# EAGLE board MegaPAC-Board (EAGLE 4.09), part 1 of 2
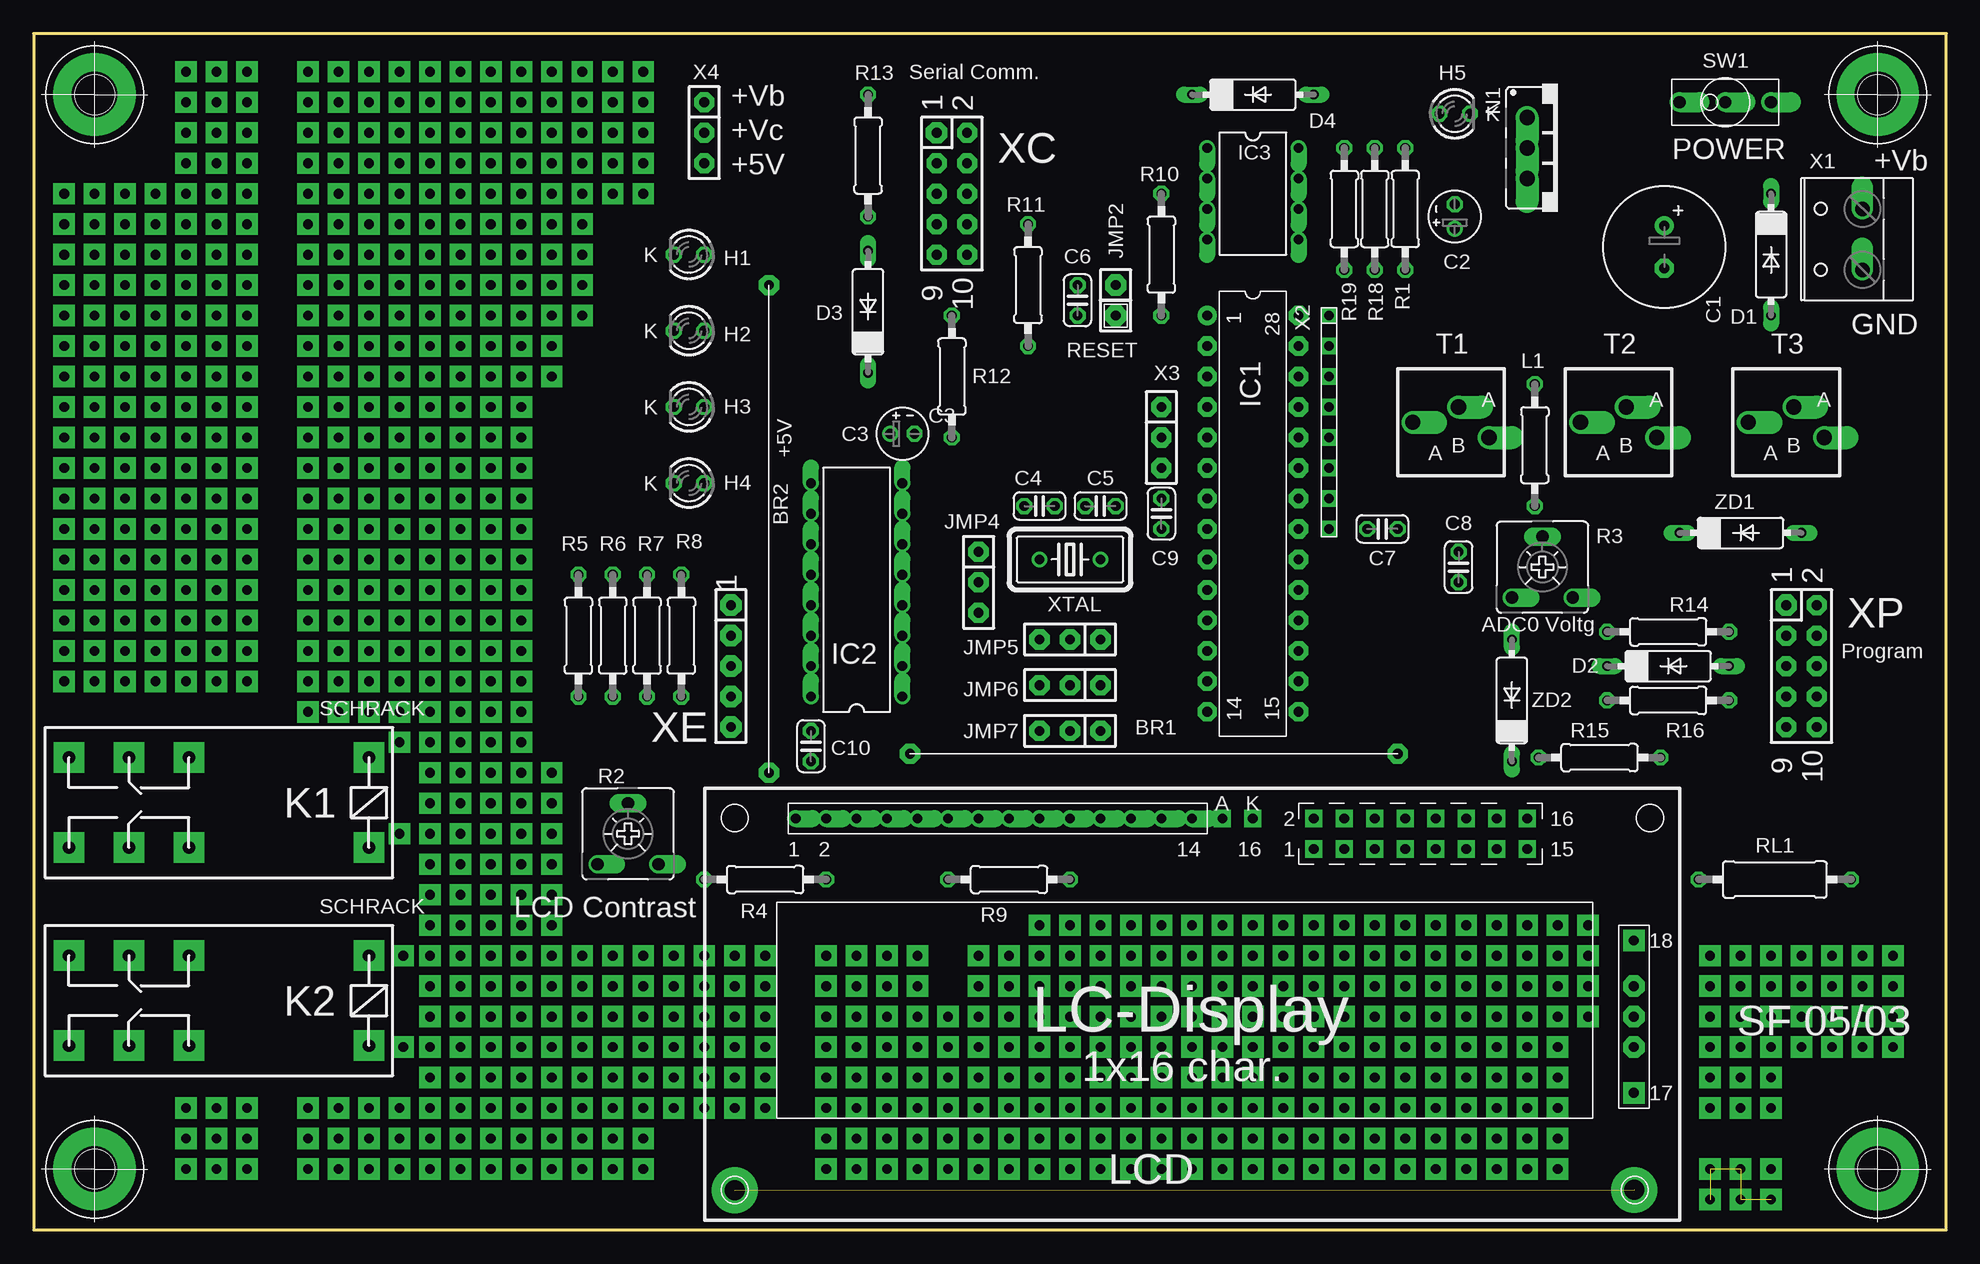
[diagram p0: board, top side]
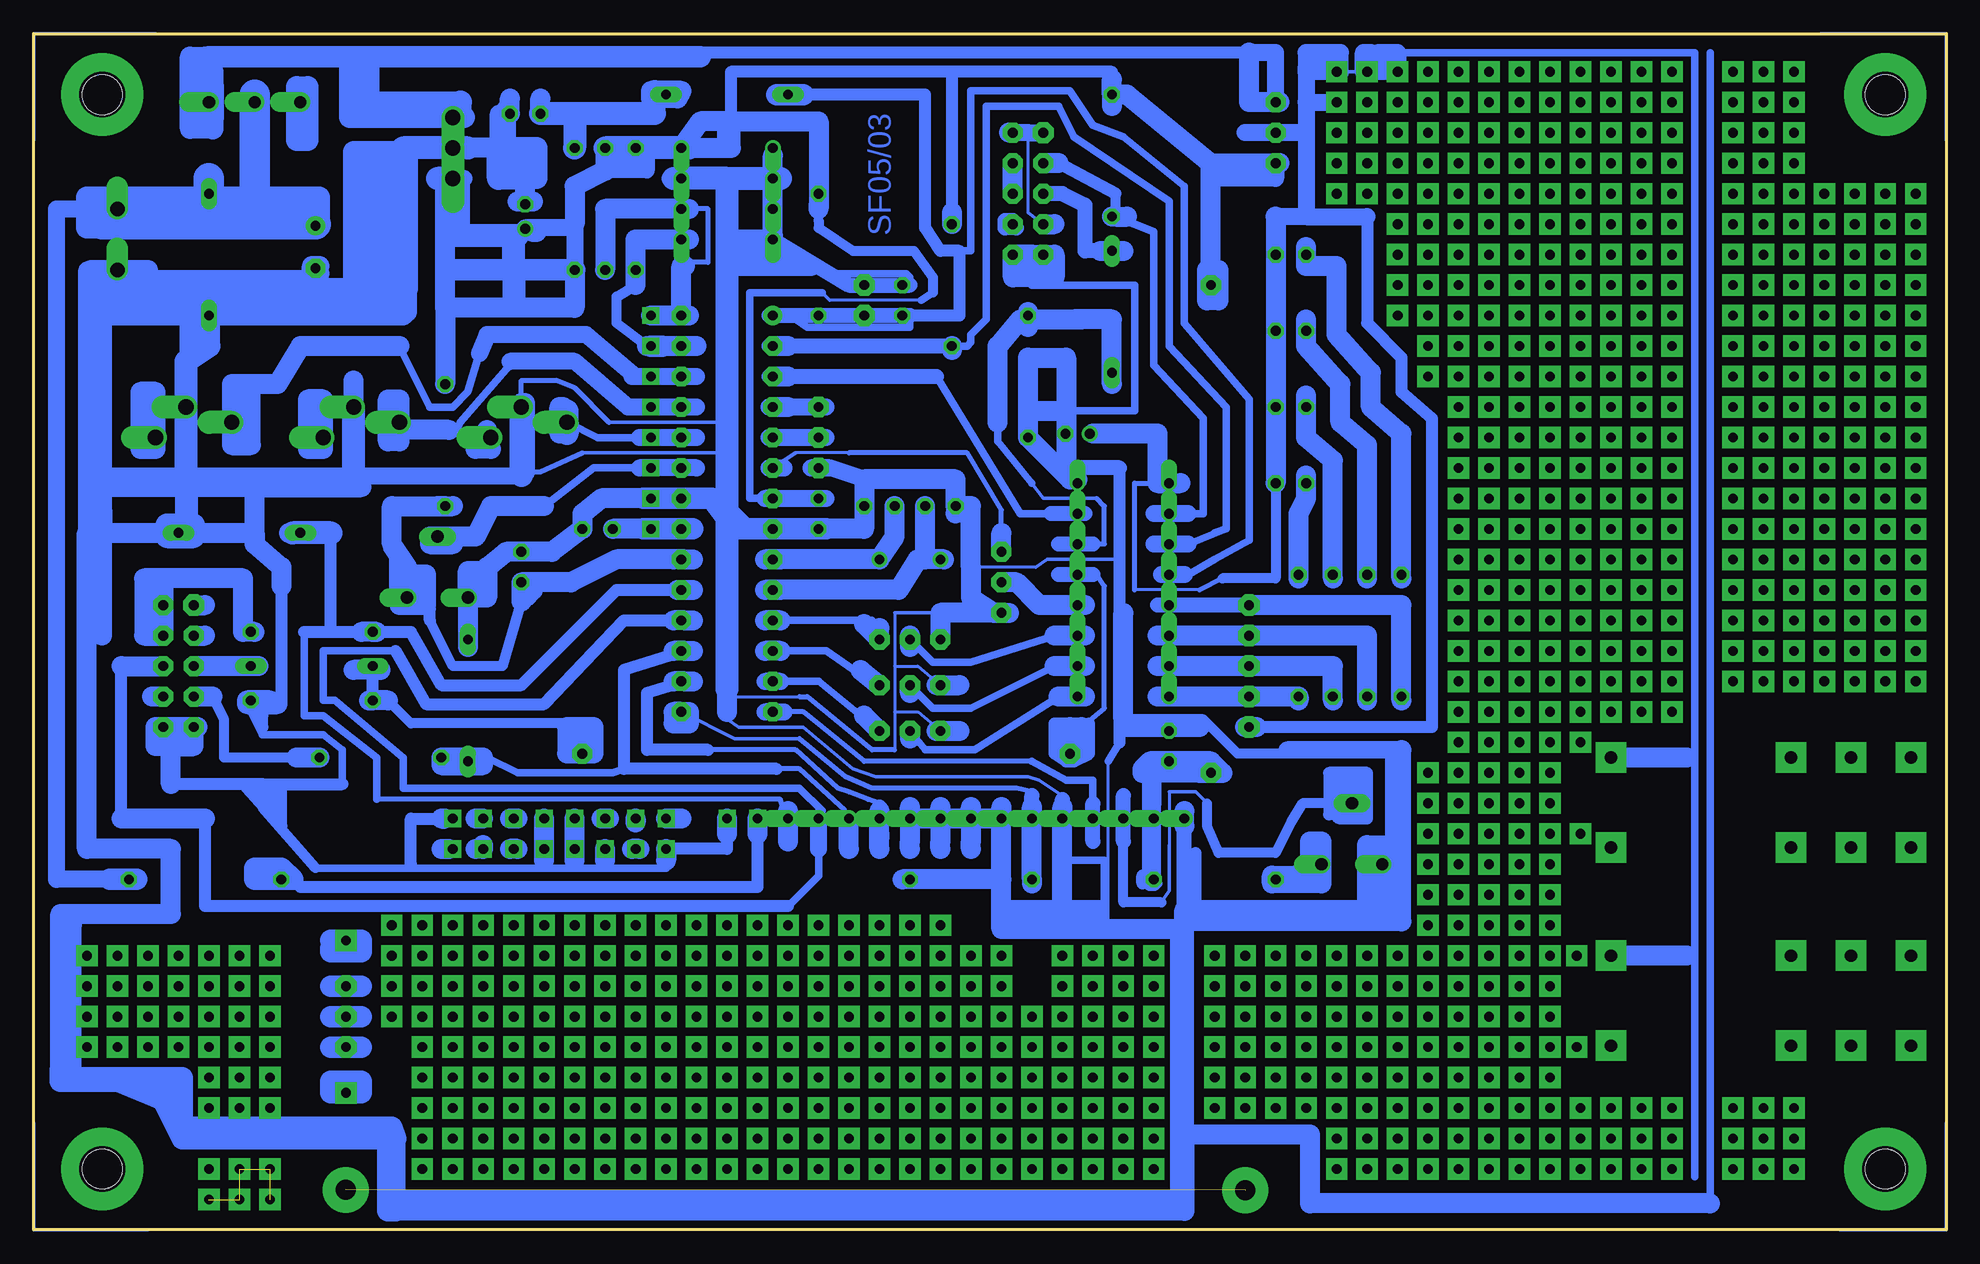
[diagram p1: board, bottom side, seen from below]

Size 159.38 x 99.69 mm. Coordinates in mm from the lower left corner, seen from the top.
Outline: 0,0 159.38,0 159.38,99.69 0,99.69 0,0
Copper layers used: Bottom

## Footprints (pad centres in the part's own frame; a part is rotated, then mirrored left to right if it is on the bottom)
40 = drill 0.813 pad 1.676 octagon: P$1 -20.32,0; P$2 20.32,0
E3,5-10 = drill 0.813 pad 1.6 round: + -1.778,0 | drill 0.813 pad 1.6 octagon: - 1.778,0
E2-4 = drill 0.813 pad 1.27 round: + -1.016,0 | drill 0.813 pad 1.27 octagon: - 1.016,0
C025-024X044 = drill 0.813 octagon: 1 -1.27,0; 2 1.27,0
DO07 = drill 0.813 long: A 5.08,0; C -5.08,0
B3,3 = drill 3.81 pad 6.858 round: P$1 0,0 | hole 3.302: 0,0
LED3MM = drill 0.813 octagon: A -1.27,0; K 1.27,0
DIL28-3 = drill 0.813 pad 1.6 round: 1 -16.51,-3.81 | drill 0.813 pad 1.6 octagon: 2 -13.97,-3.81; 3 -11.43,-3.81; 4 -8.89,-3.81; 5 -6.35,-3.81; 6 -3.81,-3.81; 7 -1.27,-3.81; 8 1.27,-3.81; 9 3.81,-3.81; 10 6.35,-3.81; 11 8.89,-3.81; 12 11.43,-3.81; 13 13.97,-3.81; 14 16.51,-3.81; 15 16.51,3.81; 16 13.97,3.81; 17 11.43,3.81; 18 8.89,3.81; 19 6.35,3.81; 20 3.81,3.81; 21 1.27,3.81; 22 -1.27,3.81; 23 -3.81,3.81; 24 -6.35,3.81; 25 -8.89,3.81; 26 -11.43,3.81; 27 -13.97,3.81; 28 -16.51,3.81
DIL16 = drill 0.813 offset: 1 -8.89,-3.81; 2 -6.35,-3.81; 3 -3.81,-3.81; 4 -1.27,-3.81; 5 1.27,-3.81; 6 3.81,-3.81; 7 6.35,-3.81; 8 8.89,-3.81; 9 8.89,3.81; 10 6.35,3.81; 11 3.81,3.81; 12 1.27,3.81; 13 -1.27,3.81; 14 -3.81,3.81; 15 -6.35,3.81; 16 -8.89,3.81
DIL08 = drill 0.813 offset: 1 -3.81,-3.81; 2 -1.27,-3.81; 3 1.27,-3.81; 4 3.81,-3.81; 5 3.81,3.81; 6 1.27,3.81; 7 -1.27,3.81; 8 -3.81,3.81
2X1X254 = drill 0.813 pad 1.778 octagon: P$1 0,0; P$2 2.54,0
3X1X254 = drill 0.813 pad 1.676 octagon: P$1 0,0; P$2 -2.54,0; P$3 2.54,0
RT-SCHRA = drill 1.016 pad 2.54 square: P$1 25,0; P$2 0,0; P$3 20,0; P$4 15,0; P$5 0,7.5; P$6 15,7.5; P$7 20,7.5; P$8 25,7.5
0207/10 = drill 0.813 octagon: 1 -5.08,0; 2 5.08,0
LCD1X16 = drill 0.813 pad 1.422 offset: P$1 5.08,-2.54; P$2 7.62,-2.54; P$3 10.16,-2.54; P$4 12.7,-2.54; P$5 15.24,-2.54; P$6 17.78,-2.54; P$7 20.32,-2.54; P$8 22.86,-2.54; P$9 25.4,-2.54; P$10 27.94,-2.54; P$11 30.48,-2.54; P$12 33.02,-2.54; P$13 35.56,-2.54; P$14 38.1,-2.54 | drill 0.813 pad 1.422 square: P$15 40.64,-2.54; P$16 43.18,-2.54; P$17 48.26,-2.54; P$18 50.8,-2.54; P$19 53.34,-2.54; P$20 55.88,-2.54; P$21 58.42,-2.54; P$22 60.96,-2.54; P$23 63.5,-2.54; P$24 66.04,-2.54; P$25 48.26,-5.08; P$26 50.8,-5.08; P$27 53.34,-5.08; P$28 55.88,-5.08; P$29 58.42,-5.08; P$30 60.96,-5.08; P$31 63.5,-5.08; P$32 66.04,-5.08 | drill 0.813 pad 1.778 octagon: P$33 74.93,-19.05; P$34 74.93,-16.51; P$35 74.93,-21.59 | drill 0.813 pad 1.778 square: P$36 74.93,-25.4; P$37 74.93,-12.7
78XXS_ = drill 1.27 pad 1.778 offset: GND 0,-2.54; IN -2.54,-2.54; OUT 2.54,-2.54
CA6V = drill 1.016 offset: A -2.54,-2.54; E 2.54,-2.54 | drill 1.016 long: S 0,2.54
0309/12 = drill 0.813 octagon: 1 -6.35,0; 2 6.35,0
MINISW = drill 1.016 pad 1.676 offset: P$1 0,0; P$2 3.81,0; P$3 -3.81,0
MPT-36 = drill 1.27 pad 1.905 offset: P$1 0.635,3.81; P$2 6.985,2.54; P$3 4.445,5.08
W237-132 = drill 1.194 offset: 1 -2.54,-0.635; 2 2.54,-0.635
8X1X254 = drill 0.813 pad 1.397 square: P$1 0,0; P$2 2.54,0; P$3 5.08,0; P$4 7.62,0; P$5 10.16,0; P$6 12.7,0; P$7 15.24,0; P$8 17.78,0
5X2X254 = drill 0.813 pad 1.676 octagon: P$1 2.54,0; P$3 5.08,0; P$4 7.62,0; P$5 10.16,0; P$6 0,0; P$7 2.54,2.54; P$8 0,2.54; P$9 5.08,2.54; P$10 7.62,2.54; P$11 10.16,2.54 | drill 0.813 pad 1.778 octagon: P$2 0,0
5X1X254 = drill 0.813 pad 1.778 octagon: P$1 2.54,0; P$2 0,0; P$3 5.08,0; P$4 7.62,0; P$5 10.16,0
HC18U-V = drill 0.813 round: 1 -2.54,0; 2 2.54,0

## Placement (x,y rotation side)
BR1  [40]  93.34,39.69 0 top
BR2  [40]  61.28,58.42 90 top
C1  [E3,5-10]  135.89,81.92 270 top
C2  [E2-4]  118.43,84.45 90 top
C3  [E2-4]  72.39,66.36 0 top
C4  [C025-024X044]  83.82,60.33 180 top
C5  [C025-024X044]  88.9,60.33 180 top
C6  [C025-024X044]  87,77.47 90 top
C7  [C025-024X044]  112.39,58.42 180 top
C8  [C025-024X044]  118.75,55.24 270 top
C9  [C025-024X044]  93.98,59.69 90 top
C10  [C025-024X044]  64.77,40.32 270 top
D1  [DO07]  144.78,81.28 270 top
D2  [DO07]  136.21,46.99 0 top
D3  [DO07]  69.53,76.52 90 top
D4  [DO07]  101.6,94.61 0 top
E$1  [B3,3]  5.08,94.61 0 top
E$2  [B3,3]  5.08,5.08 0 top
E$3  [B3,3]  153.67,5.08 0 top
E$4  [B3,3]  153.67,94.61 0 top
H1  [LED3MM]  54.61,81.28 180 top
H2  [LED3MM]  54.61,74.93 180 top
H3  [LED3MM]  54.61,68.58 180 top
H4  [LED3MM]  54.61,62.23 180 top
H5  [LED3MM]  118.43,93.03 0 top
IC1  ATmega8  [DIL28-3]  101.6,59.69 270 top
IC2  ULN2003  [DIL16]  68.58,53.34 90 top
IC3  X24C16  [DIL08]  101.6,86.36 270 top
JMP2  [2X1X254]  90.17,76.2 90 top
JMP4  [3X1X254]  78.74,53.98 270 top
JMP5  [3X1X254]  86.36,49.21 180 top
JMP6  [3X1X254]  86.36,45.4 180 top
JMP7  [3X1X254]  86.36,41.59 180 top
K1  [RT-SCHRA]  27.94,39.37 180 top
K2  [RT-SCHRA]  27.94,22.86 180 top
L1  [0207/10]  125.09,65.41 270 top
LCD  [LCD1X16]  58.42,36.83 0 top
N1  [78XXS_]  127,90.17 270 top
R1  [0207/10]  114.3,85.09 90 top
R2  [CA6V]  49.53,33.02 0 top
R3  [CA6V]  125.73,55.24 0 top
R4  [0207/10]  60.96,29.21 0 top
R5  [0207/10]  45.4,49.53 90 top
R6  [0207/10]  48.26,49.53 90 top
R7  [0207/10]  51.12,49.53 90 top
R8  [0207/10]  53.98,49.53 90 top
R9  [0207/10]  81.28,29.21 0 top
R10  [0207/10]  93.98,81.28 90 top
R11  [0207/10]  82.87,78.74 90 top
R12  [0207/10]  76.52,71.12 90 top
R13  [0207/10]  69.53,89.53 270 top
R14  [0207/10]  136.21,49.85 0 top
R15  [0207/10]  130.49,39.37 0 top
R16  [0207/10]  136.21,44.13 0 top
R18  [0207/10]  109.22,85.09 270 top
R19  [0207/10]  111.76,85.09 270 top
RL1  [0309/12]  145.1,29.21 0 top
SW1  [MINISW]  140.97,93.98 0 top
T1  [MPT-36]  114.3,63.5 0 top
T2  [MPT-36]  128.27,63.5 0 top
T3  [MPT-36]  142.24,63.5 0 top
X1  [W237-132]  151.76,82.55 90 top
X2  [8X1X254]  107.95,76.2 270 top
X3  [3X1X254]  93.98,66.04 270 top
X4  [3X1X254]  55.88,91.44 270 top
XC  [5X2X254]  75.25,91.44 270 top
XE  [5X1X254]  58.1,52.07 270 top
XP  [5X2X254]  146.05,52.07 270 top
XTAL  [HC18U-V]  86.36,55.88 0 top
ZD1  [DO07]  142.24,58.1 0 top
ZD2  [DO07]  123.19,44.13 90 top

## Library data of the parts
BR1 BR2 = jumper
C1-C10 L1 R1 R4-R16 R18 R19 RL1 = rcl
D1-D4 ZD1 ZD2 = diode
E$1-E$4 = HOLES
H1-H5 = led
IC1 LCD = PIC
IC2 IC3 = dil
JMP2 JMP4-JMP7 X2-X4 XC XE XP = BERG
K1 K2 = RELAIS
N1 = v-reg
R2 R3 = pot
SW1 = switches
T1-T3 = KEY
X1 = con-wago-508
XTAL = crystal

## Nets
S$5: XP.P$2
S$6: H5.A R1.2
S$7: T2.P$1
S$12: N1.OUT
S$13: JMP4.P$1
S$16: XP.P$1
S$17: JMP5.P$1
S$18: R18.2
S$26: XE.P$2
S$27: C7.2
S$29: XC.P$2 XC.P$4 XC.P$8
S$35: C4.1
S$38: JMP7.P$2
S$42: XP.P$3
S$43: R15.1
S$45: XP.P$4
S$46: C5.2 XTAL.2
S$47: JMP6.P$2
S$48: JMP5.P$2
S$49: JMP7.P$1
S$50: XE.P$1
S$51: IC1.6 JMP4.P$2
S$52: XE.P$3
S$53: R8.1 XE.P$4
S$54: XC.P$3
S$55: JMP6.P$1
S$56: T3.P$1
S$67: XC.P$1
S$69: LCD.P$4
S$70: R9.1
S$71: LCD.P$11
S$72: XP.P$7 XP.P$8
S$73: D2.C R16.1
S$74: XP.P$10
S$77: XP.P$9
S$79: D4.C IC2.12
S$81: XC.P$7 XC.P$9
S$85: XC.P$10
S$90: IC2.11
S$91: D1.C X1.2
S$92: LCD.P$17
S$93: IC2.10
S$94: IC2.6
S$99: LCD.P$16 LCD.P$20 LCD.P$21 LCD.P$25 LCD.P$27
S$127: H4.A IC2.9
S$686: K1.P$2
S$706: H5.K
S$709: K2.P$2
S$880: LCD.P$18
S$883: LCD.P$31
S$884: LCD.P$23
S$899: R19.2
S$911: C7.1 D1.A IC2.8 IC3.2 IC3.4 JMP5.P$3 JMP6.P$3 JMP7.P$3 LCD.P$10 R3.A T1.P$3 T2.P$3 T3.P$3 X1.1 XC.P$5 XC.P$11
S$917: L1.1 R1.1 R19.1
S$921: LCD.P$15

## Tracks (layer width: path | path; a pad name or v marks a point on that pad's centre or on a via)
S$1
  Bottom 0.254: 0,99.69 10.48,99.69
  Bottom 0.305: 0,90.81 0,99.69
S$2
  Bottom 0.305: 0,8.89 0,0 8.89,0
S$3
  Bottom 0.305: 149.86,0 159.38,0 159.38,8.89
S$4
  Bottom 0.305: 159.38,90.81 159.38,99.69 149.22,99.69
S$5
  Bottom 1.422: XP.P$2 145.73,52.07
  Bottom 1.676: XP.P$2 145.1,52.07
S$6
  Bottom 1.422: 107.63,93.03 107.63,94.61 105.41,94.61
  Bottom 1.676: H5.A 117.16,94.3
  Bottom 1.778: 107.63,93.03 107.63,94.93
  Bottom 1.93: 114.3,93.03 R1.2 | 114.3,93.03 H5.A | 107.63,93.03 114.3,93.03
S$7
  Bottom 0.61: 119.7,72.07 123.83,67.31 124.14,66.67 124.78,66.67
  Bottom 1.676: 124.78,66.67 128.91,66.67 T2.P$1
S$8
  Bottom 1.676: 104.78,76.2 107.95,76.2
S$9
  Bottom 2.54: 135.89,83.82 140.97,83.82 | 140.97,83.82 153.67,83.82 | 140.97,83.82 140.97,94.61
S$10
  Bottom 1.676: 81.28,31.75 81.28,32.38
S$11
  Bottom 1.27: 77.79,84.14 78.42,84.14 78.42,83.5 77.47,83.5
S$12
  Bottom 1.422: 123.51,87.63 N1.OUT
S$13
  Bottom 1.676: 71.75,52.07 75.56,52.07 77.47,53.98 JMP4.P$1
S$14
  Bottom 1.676: 97.79,82.87 97.79,89.53
S$15
  Bottom 1.676: 86.36,44.77 86.36,45.4
S$16
  Bottom 1.676: XP.P$1 145.1,49.53
S$17
  Bottom 0.61: JMP5.P$1 84.45,47.31 81.28,47.31 74.3,49.53
  Bottom 1.676: 71.75,49.53 74.3,49.53 | 86.36,49.53 JMP5.P$1 86.36,48.58
S$18
  Bottom 0.813: 109.22,78.74 110.81,77.79 110.81,75.56 108.27,73.66
  Bottom 1.676: 104.78,82.55 109.22,82.55 R18.2 109.22,78.74 | 104.14,73.66 107,73.66 | 107.95,73.66 108.27,73.66
  Bottom 1.778: 107,73.66 107.95,73.66
S$19
  Bottom 1.422: 98.11,63.5 96.84,63.5
S$21
  Bottom 0.61: 86.36,75.88 86.36,75.25 94.93,75.25 95.89,75.88
S$22
  Bottom 1.422: 104.14,71.12 109.54,71.12
S$23
  Bottom 1.422: 104.14,68.58 109.86,68.58 114.3,72.39 119.7,72.39
S$24  (via drill 0.81 pad 1.78)
  other vias: 25.4,93.98
S$25
  Bottom 1.676: 83.82,31.75 83.82,32.38
S$26
  Bottom 1.27: XE.P$2 65.72,52.07
  Bottom 1.676: 45.4,44.13 45.4,52.07 XE.P$2
S$27
  Bottom 1.676: 108.58,58.42 C7.2
  Bottom 1.778: 104.46,58.42 108.58,58.42
S$28
  Bottom 1.27: 86.36,76.2 98.11,76.2
S$29
  Bottom 0.254: 76.52,84.77 76.52,91.44
  Bottom 0.305: XC.P$4 76.52,84.77
  Bottom 1.422: XC.P$2 76.52,91.44 XC.P$8
  Bottom 1.676: XC.P$4 74.3,83.82 | XC.P$8 78.11,91.44
S$30
  Bottom 1.27: 97.79,73.66 98.11,73.66 | 87,73.66 96.52,73.66
  Bottom 1.676: 96.52,73.66 97.79,73.66
S$31
  Bottom 1.422: 97.79,68.58 98.11,68.58 | 93.34,68.58 96.52,68.58
  Bottom 1.676: 96.52,68.58 97.79,68.58
S$32
  Bottom 1.422: 93.34,66.04 98.11,66.04
S$33
  Bottom 0.406: 130.81,35.88 97.16,35.88 96.84,34.92
  Bottom 0.61: 136.84,49.85 136.84,42.86 135.25,42.86 130.81,39.37 130.81,35.88
  Bottom 1.016: 134.62,58.1 134.62,49.85 135.57,49.85 | 136.84,49.85 135.57,49.85 | 130.81,49.85 127.95,49.85 125.41,45.4 118.75,45.4 110.81,53.34 106.36,53.34 | 135.57,49.85 131.13,49.85
  Bottom 1.676: 137.79,58.1 138.11,58.1 | 130.81,49.85 131.13,49.85 132.08,49.85
  Bottom 1.93: 134.62,58.1 137.79,58.1
S$34
  Bottom 0.61: 116.84,60.33 112.71,63.5 108.9,63.5
  Bottom 1.422: 104.14,63.5 108.9,63.5
  Bottom 1.676: 116.84,60.33 121.28,60.33 122.56,57.78 126.36,57.78 126.36,57.15 124.46,57.15
S$35
  Bottom 1.676: 97.79,53.34 98.42,53.34 | 97.79,53.34 97.16,53.34 | 97.79,53.34 87.31,53.34 85.72,55.88 85.09,55.88 | 83.5,55.88 85.09,55.88 | 85.09,55.88 C4.1
S$36
  Bottom 1.676: 97.16,50.8 98.42,50.8
S$37
  Bottom 1.676: 97.16,48.26 98.42,48.26
S$38
  Bottom 0.61: 97.16,45.72 93.98,45.72 JMP7.P$2
  Bottom 1.422: 97.16,45.72 98.42,45.72
  Bottom 1.676: JMP7.P$2 90.17,42.86
S$39
  Bottom 1.676: 86.36,31.75 86.36,32.38
S$40
  Bottom 1.676: 125.09,60.33 124.46,60.33 | 125.09,60.33 125.73,60.33 | 125.09,60.33 129.54,60.33 129.54,57.15 128.27,55.24 128.27,52.07 127.64,52.07 | 128.91,55.88 128.91,52.07 127.64,52.07 | 127.95,54.61 126.68,54.61 126.68,52.07 127.64,52.07
S$41
  Bottom 1.676: 105.73,53.34 104.46,53.34
S$42
  Bottom 1.676: 140.65,46.99 XP.P$3
S$43
  Bottom 0.406: 91.76,34.92 95.57,38.42 97.47,38.42
  Bottom 0.61: 110.17,38.42 111.12,38.1 119.06,38.1 121.6,39.37
  Bottom 1.016: 105.09,48.26 110.17,46.67 110.17,38.42 97.47,38.42 | 121.6,39.37 121.92,39.37
  Bottom 1.676: 104.46,48.26 105.09,48.26 106.05,48.26 | 121.92,39.37 R15.1 125.41,38.73 121.92,38.73
S$44
  Bottom 1.676: 149.22,65.09 150.5,65.09 150.5,69.85 149.22,69.85 149.22,65.41
S$45
  Bottom 0.813: 137.48,39.37 143.51,39.37 143.51,42.55 144.46,44.45
  Bottom 1.676: 144.46,44.45 XP.P$4 | 135.57,39.37 137.48,39.37
S$46
  Bottom 1.676: C5.2 87.63,57.78 XTAL.2 97.79,55.88 | 97.79,55.88 98.42,55.88 | 97.79,55.88 97.16,55.88
S$47
  Bottom 0.61: 96.52,48.26 93.34,48.26 89.22,45.4 90.49,46.67
  Bottom 1.676: JMP6.P$2 90.49,46.67
S$48
  Bottom 0.61: 88.9,50.16 89.53,50.8 96.52,50.8
  Bottom 1.676: JMP5.P$2 88.9,50.16
S$49
  Bottom 0.61: JMP7.P$1 85.09,40.01 80.96,40.01 73.98,44.45
  Bottom 1.676: 71.75,44.45 73.98,44.45 | 86.36,41.27 JMP7.P$1 86.36,40.96
S$50
  Bottom 1.676: 48.26,44.13 48.26,49.53 XE.P$1 65.72,49.53
S$51
  Bottom 0.254: 91.44,64.77 95.89,64.77
  Bottom 0.305: 95.89,64.77 IC1.6
  Bottom 0.406: 91.44,64.77 81.6,64.77 78.74,60.01 78.74,58.1
  Bottom 1.676: JMP4.P$2 78.74,58.1
S$52
  Bottom 1.676: 51.12,44.13 51.12,46.99 XE.P$3 65.72,46.99
S$53
  Bottom 1.676: 53.98,44.13 R8.1 XE.P$4 65.72,44.45
S$54
  Bottom 1.27: XC.P$3 73.66,86.36 71.75,85.41 71.75,81.6 70.48,81.6 69.22,81.6
  Bottom 1.676: 70.48,81.6 68.58,81.6
S$55
  Bottom 0.61: 74.3,46.99 81.28,43.5 84.45,43.5 JMP6.P$1
  Bottom 1.676: 71.75,46.99 74.3,46.99
S$56
  Bottom 0.61: 128.91,73.66 126.36,68.58 124.46,68.58 123.19,69.85 122.24,73.03
  Bottom 1.422: 109.22,71.12 113.35,74.61 121.6,74.61 122.24,73.03
  Bottom 1.676: 128.91,73.66 137.16,73.66 139.06,70.48 142.88,70.48 T3.P$1 142.88,65.41 141.29,65.41 141.29,69.85
S$57
  Bottom 1.676: 53.98,54.29 53.98,59.69 53.34,60.96 53.34,62.87
S$58
  Bottom 1.676: 51.12,54.29 51.12,64.14 53.34,66.04 53.34,69.53
S$59
  Bottom 1.676: 53.34,75.88 53.34,73.66 50.48,70.48 50.48,67.31 48.26,65.41 48.26,54.29
S$60
  Bottom 1.676: 45.4,54.29 45.4,66.36 47.94,68.58 47.94,71.44 50.8,74.61 50.8,80.33 53.34,80.33 53.34,81.92
S$61
  Bottom 1.016: 58.1,98.11 137.16,98.11
  Bottom 1.422: 55.88,93.98 55.88,98.11 58.1,98.11
  Bottom 1.676: 58.1,98.11 58.1,93.98 55.88,93.98 55.56,93.98
S$62
  Bottom 1.676: 48.9,37.47 50.8,37.47
S$63
  Bottom 1.676: 128.91,66.04 128.91,69.22 129.86,69.22 129.86,65.72 128.91,65.72
S$64  (via drill 0.81 pad 1.78)
  other vias: 27.94,93.98
S$65
  Bottom 0.813: 65.72,28.89 66.04,28.89
  Bottom 1.016: 66.04,28.89 66.99,28.89 66.99,29.53 66.67,29.53
  Bottom 1.27: 66.04,35.56 66.04,28.89 66.36,28.89 66.36,37.47
S$66
  Bottom 1.676: 53.02,29.53 53.02,32.38 52.07,32.38 52.07,28.89 56.2,28.89 56.2,29.53 54.29,29.53
S$67
  Bottom 0.813: 69.22,84.14 69.22,86.36
  Bottom 1.016: 69.22,86.36 73.98,88.9
  Bottom 1.676: 73.98,88.9 XC.P$1
S$68
  Bottom 1.27: 66.04,38.1 66.04,35.88
  Bottom 1.676: 61.28,38.1 60.64,38.1 | 61.91,38.1 61.28,38.1 | 61.28,39.05 61.28,38.1 | 61.28,39.05 66.36,39.05 66.99,38.42 | 61.28,39.05 60.33,38.1 61.91,38.1 | 61.91,38.1 62.23,38.1 | 61.91,38.1 66.04,38.1 66.99,38.1
S$69
  Bottom 0.406: 76.2,39.05 90.17,39.05 95.25,43.18 97.79,43.18
  Bottom 0.61: 76.2,39.05 73.34,37.47 71.12,37.47 71.12,35.56 LCD.P$4
  Bottom 1.27: 71.12,32.38 71.12,35.56
  Bottom 1.422: 96.84,43.18 97.79,43.18 98.42,43.18
S$70
  Bottom 0.305: 95.57,40.96 100.97,40.96 105.41,43.18
  Bottom 0.406: 76.2,36.2 76.2,36.51 77.47,36.83 89.53,36.83 91.76,37.78 95.57,40.96
  Bottom 1.27: 76.2,35.24 76.2,36.2
  Bottom 1.676: 76.2,34.29 R9.1 76.2,28.89 | 76.2,34.29 76.2,34.92 | 76.2,34.29 76.2,35.24 | 105.41,43.18 104.78,43.18 104.78,42.23 106.05,42.23 106.05,43.18 105.41,43.18
S$71
  Bottom 0.406: 88.9,35.56 89.85,35.88 91.44,36.51 92.39,36.83 95.89,40.01 103.19,40.01
  Bottom 0.61: 88.9,34.92 LCD.P$11 | 88.9,35.24 88.9,35.56
  Bottom 1.016: 103.19,40.01 108.27,40.01 108.27,44.77 105.09,45.72
  Bottom 1.27: 88.9,34.92 88.9,35.24
  Bottom 1.676: 104.46,45.72 105.09,45.72 106.05,45.72 | 88.9,33.02 88.9,34.92 | 88.9,33.02 88.9,32.7 | 88.9,31.75 88.9,33.02
S$72
  Bottom 1.676: 148.59,54.29 XP.P$8 XP.P$7 150.18,49.53 150.18,54.29 148.59,54.29 | 148.59,54.29 141.92,54.29 141.92,49.85 140.97,49.85
S$73
  Bottom 0.813: 113.67,39.69 113.67,42.23 127.95,42.23 129.86,44.13
  Bottom 1.016: D2.C 133.03,46.67 132.72,46.67 | R16.1 131.13,46.67
  Bottom 1.676: 114.62,39.69 113.67,39.69 112.71,39.69 112.71,41.91 114.94,41.91 114.94,39.69 | 129.86,44.13 R16.1 131.44,44.13 | 130.49,46.67 131.13,46.67 132.72,46.67
S$74
  Bottom 1.676: XP.P$10 149.54,44.45
S$75
  Bottom 0.61: 129.22,48.26 135.25,48.26 135.25,44.13 134.3,44.13 128.59,39.37 128.59,36.83 95.57,36.83 93.66,34.92
  Bottom 1.016: 105.09,50.8 110.17,50.8 116.84,43.81 126.68,43.81 129.22,48.26
  Bottom 1.676: 104.46,50.8 105.09,50.8 106.05,50.8
S$76
  Bottom 1.676: 91.44,31.75 91.44,33.97
S$77
  Bottom 0.61: 96.52,26.99 93.98,29.53 93.98,31.75 | 93.98,34.29 93.98,34.92
  Bottom 1.016: 96.52,26.99 145.1,26.99 145.1,34.29 | 152.08,34.29 152.08,46.99
  Bottom 1.422: 93.98,31.75 93.98,34.29
  Bottom 1.676: 152.08,46.99 XP.P$9 | 145.1,34.29 152.08,34.29
S$78
  Bottom 1.778: 148.27,12.06 148.27,11.11
S$79
  Bottom 0.61: 82.23,81.6 81.28,81.6 81.28,94.93 73.03,94.93 71.12,92.08 68.58,91.12 63.5,87 63.5,75.56 58.1,69.22 58.1,57.47 60.96,55.88 63.18,54.61 63.5,54.61 IC2.12
  Bottom 1.016: 86.04,76.2 82.23,76.2 82.23,81.6 83.82,81.6 85.09,83.5 85.09,94.61 95.25,94.61 D4.C
  Bottom 1.422: 63.5,54.61 65.41,54.61
  Bottom 1.778: 95.25,94.61 97.47,94.61
S$80
  Bottom 1.676: 69.53,70.48 69.53,75.88 72.71,75.88
S$81
  Bottom 1.676: XC.P$9 XC.P$7
S$82
  Bottom 1.676: 135.25,65.09 136.53,65.09 136.53,69.22 135.25,69.22 135.25,65.41
S$83
  Bottom 1.676: 76.52,75.25 76.52,76.52
S$84
  Bottom 1.676: 72.39,39.69 73.66,39.69
S$86
  Bottom 0.61: 108.9,66.04 112.39,66.04 114.94,67.31
  Bottom 1.422: 104.14,66.04 108.9,66.04 | 114.94,66.36 114.62,66.67
  Bottom 1.676: 115.25,68.58 115.57,68.58 115.57,66.36 114.94,66.36
  Bottom 1.93: 114.94,66.36 114.94,67.31 114.94,68.26
S$87
  Bottom 0.61: 73.34,30.8 70.17,30.8 70.17,27.3
S$88
  Bottom 0.406: 70.8,54.61 70.17,53.66 70.17,43.5 72.07,41.91
  Bottom 1.676: 73.03,39.37 73.03,41.91 72.07,41.91
S$89
  Bottom 1.422: 51.44,97.16 53.02,97.16
S$90
  Bottom 0.61: IC2.11 63.18,57.15 60.01,58.42 | 60.01,58.42 60.96,58.1 | 60.01,58.42 60.01,68.58 64.77,73.66 64.77,85.72 72.71,91.12 73.98,93.66 80.01,93.66 80.01,75.88 81.28,74.61 81.28,73.98 81.6,73.66 82.87,73.66
  Bottom 1.27: 82.87,73.66 86.68,73.66
  Bottom 1.422: 63.18,57.15 66.04,57.15
  Bottom 1.676: 82.87,73.66 82.87,73.34
S$91
  Bottom 0.813: 144.78,85.09 136.53,85.09
  Bottom 1.422: 153.03,29.21 157.48,29.21 157.48,29.84 | X1.2 153.67,85.09 157.48,85.09 157.48,29.84 | 157.48,29.84 157.48,29.53
  Bottom 1.778: 150.81,29.21 153.03,29.21
  Bottom 2.54: 144.78,87.63 D1.C 144.78,85.09 153.67,85.09
S$92
  Bottom 1.676: 105.41,34.29 LCD.P$17
S$93
  Bottom 0.61: 69.22,84.45 66.04,83.19 66.04,72.07 61.91,67.63 61.91,59.69 63.18,59.69 IC2.10
  Bottom 1.422: 63.18,59.69 66.04,59.69
  Bottom 1.676: 68.26,84.45 69.22,84.45 69.53,84.45
S$94
  Bottom 0.305: 70.8,60.96 75.25,60.96 76.2,62.23 | 71.12,57.15 IC2.6
  Bottom 0.406: 70.8,60.96 70.17,60.33 70.17,57.15 71.12,57.15
  Bottom 0.61: 76.2,62.23 79.06,65.72 79.06,67.31
  Bottom 1.27: 71.12,57.15 73.98,57.15
  Bottom 1.676: 72.07,75.88 77.15,75.88 79.06,73.66 79.06,67.31
S$95
  Bottom 1.27: 71.75,59.69 74.61,59.69
S$96
  Bottom 0.61: 74.3,59.69 77.15,59.69 84.14,71.12
  Bottom 1.27: 97.79,71.12 98.11,71.12 | 84.14,71.12 96.52,71.12
  Bottom 1.676: 96.52,71.12 97.79,71.12
S$97
  Bottom 1.27: 71.12,54.61 73.98,54.61
S$98  (via drill 0.81 pad 1.78)
  other vias: 30.48,93.98
S$99
  Bottom 0.61: 147.96,39.69 147.96,40.32 | 140.34,35.24 140.34,37.15 | 124.14,30.16 123.83,30.16 | 124.14,30.16 135.89,30.16 | 116.84,30.16 116.84,30.8 | 116.84,30.16 124.14,30.16 | 114.3,30.16 114.3,30.8 | 114.3,30.16 116.84,30.16 | 111.76,30.16 111.76,30.8 | 111.76,30.16 114.3,30.16 | 111.76,30.16 106.68,30.16 106.68,30.8
  Bottom 0.813: 135.89,30.16 140.34,35.24
  Bottom 1.016: 133.67,37.15 140.34,37.15 147.96,37.15 | LCD.P$25 101.6,31.75 101.6,33.02
  Bottom 1.676: 146.05,41.91 148.91,41.91 | 146.05,41.91 145.73,41.91 | 149.22,41.91 149.22,40.32 147.96,40.32 146.05,40.32 146.05,41.91 | 147.96,37.15 147.96,39.69 | 116.84,30.8 LCD.P$21 | 114.3,30.8 LCD.P$20 | 111.76,30.8 LCD.P$27 | 101.6,33.02 LCD.P$16 | LCD.P$25 106.68,30.8
S$100
  Bottom 1.016: 138.75,36.83 138.75,33.66 141.6,36.83
S$101
  Bottom 1.676: 137.79,29.21 139.7,29.21
  Bottom 1.778: 137.79,29.21 138.75,30.16 140.97,30.16 140.97,29.21 137.79,29.21
S$104
  Bottom 1.676: 81.28,34.29 81.28,35.24
S$105
  Bottom 1.676: 86.36,34.29 86.36,35.24
S$106
  Bottom 1.676: 96.52,32.38 96.52,34.92
S$107
  Bottom 1.676: 153.67,60.01 153.67,77.47 | 153.67,60.01 153.67,58.1 | 153.67,49.53 153.67,60.01
S$109
  Bottom 0.813: 126.36,50.8 124.46,46.99 120.33,46.99 118.75,52.39
  Bottom 1.016: 126.36,50.8 126.36,51.75
  Bottom 1.676: 118.75,52.39 118.75,53.98 114.62,53.98 110.81,55.88 105.09,55.88 | 105.09,55.88 104.46,55.88 | 105.09,55.88 106.05,55.88
S$110
  Bottom 1.676: 47.31,27.62 47.31,30.48
S$111
  Bottom 1.676: 74.61,80.33 77.15,80.33
S$112
  Bottom 1.676: 121.28,65.09 122.56,65.09 121.6,66.67
S$113
  Bottom 1.676: 118.75,68.9 118.43,68.9 118.43,63.18
S$114
  Bottom 1.422: 122.24,54.29 122.24,53.34
S$115
  Bottom 0.254: 64.77,36.51 64.77,32.07
  Bottom 0.305: 65.41,27.3 64.77,28.26 64.77,32.07 | 64.77,36.51 62.55,36.51 61.59,35.56
  Bottom 0.813: 68.58,34.29 68.58,32.38 68.58,27.3 65.41,27.3 | 61.59,35.56 61.59,33.66 60.64,31.43 55.88,31.43 54.61,33.97 53.66,35.56 50.48,35.56
  Bottom 1.27: 68.58,32.38 68.58,36.2
  Bottom 1.676: 50.48,34.92 50.48,35.56 50.48,36.51 48.9,36.51 48.9,34.92 50.48,34.92 | 50.48,34.92 50.48,34.61 48.9,34.61
S$116
  Bottom 1.676: 62.23,41.91 68.26,41.91
S$117
  Bottom 1.676: 123.83,83.5 123.83,87.31
S$118
  Bottom 1.676: 60.64,77.47 60.64,80.01 61.59,80.01 61.59,77.47 60.64,77.47
S$119  (via drill 0.81 pad 1.78)
  other vias: 33.02,93.98
S$120
  Bottom 1.422: 106.05,87.63 106.36,87.63
S$121  (via drill 0.81 pad 1.78)
  other vias: 35.56,93.98
S$122  (via drill 0.81 pad 1.78)
  other vias: 38.1,93.98
S$123  (via drill 0.81 pad 1.78)
  other vias: 40.64,93.98
S$124  (via drill 0.81 pad 1.78)
  other vias: 43.18,93.98
S$125  (via drill 0.81 pad 1.78)
  other vias: 45.72,93.98
S$126  (via drill 0.81 pad 1.78)
  other vias: 48.26,93.98
S$127  (via drill 0.81 pad 1.78)
  Bottom 0.254: 62.23,53.34 67.63,53.34
  Bottom 0.305: 48.58,96.52 50.48,96.52
  Bottom 0.406: IC2.9 65.72,62.23 67.63,62.23 67.63,53.34 | 60.33,54.29 62.23,53.34
  Bottom 0.61: 45.72,98.11 20.95,98.11 20.95,4.45 | 47.31,98.11 47.94,98.11
  Bottom 0.813: 60.33,54.29 55.88,54.29 H4.A
  Bottom 1.016: 48.26,84.45 48.26,75.56 45.4,72.71 45.4,69.85 42.86,67.63 42.86,41.91 57.47,41.91 | 58.42,41.91 58.74,41.91
  Bottom 1.422: v48.26,96.52 48.26,98.11 47.94,98.11 | 50.8,96.52 53.34,96.52 53.34,93.98 | 53.34,93.98 53.34,91.44 | 53.34,91.44 58.42,91.44 | 53.34,84.45 55.88,84.45 | 53.34,91.44 53.34,84.45 | 53.34,84.45 48.26,84.45 | 50.8,96.52 50.8,98.11 53.34,98.11 53.34,96.84 | 47.94,98.11 47.94,96.52 v48.26,96.52 | v48.26,96.52 48.58,96.52 48.58,98.11 47.94,98.11 | 50.8,96.52 50.48,96.52 50.48,98.11 | v48.26,96.52 v45.72,96.52 45.72,98.11 47.31,98.11 | 53.34,93.98 v50.8,93.98
  Bottom 1.676: 71.12,66.36 65.72,66.36 65.72,62.23 63.82,62.23 | 55.88,84.45 H4.A | 57.47,41.91 58.42,41.91
S$128
  Bottom 1.676: 105.41,94.93 107.95,94.93 107.95,94.3 105.73,94.3 105.41,94.93
S$129
  Bottom 1.676: 119.06,85.72 117.79,85.72
S$130  (via drill 0.81 pad 1.78)
  other vias: 50.8,91.44
S$131  (via drill 0.81 pad 1.78)
  other vias: 48.26,91.44
S$132  (via drill 0.81 pad 1.78)
  other vias: 45.72,91.44
S$133  (via drill 0.81 pad 1.78)
  other vias: 43.18,91.44
S$134  (via drill 0.81 pad 1.78)
  other vias: 40.64,91.44
S$135  (via drill 0.81 pad 1.78)
  other vias: 38.1,91.44
S$136  (via drill 0.81 pad 1.78)
  other vias: 35.56,91.44
S$137  (via drill 0.81 pad 1.78)
  other vias: 33.02,91.44
S$138  (via drill 0.81 pad 1.78)
  other vias: 30.48,91.44
S$139  (via drill 0.81 pad 1.78)
  other vias: 27.94,91.44
S$140  (via drill 0.81 pad 1.78)
  other vias: 25.4,91.44
S$141  (via drill 0.81 pad 1.78)
  other vias: 25.4,88.9
S$142  (via drill 0.81 pad 1.78)
  other vias: 27.94,88.9
S$143  (via drill 0.81 pad 1.78)
  other vias: 30.48,88.9
S$144  (via drill 0.81 pad 1.78)
  other vias: 33.02,88.9
S$145  (via drill 0.81 pad 1.78)
  other vias: 35.56,88.9
S$146  (via drill 0.81 pad 1.78)
  other vias: 38.1,88.9
S$147  (via drill 0.81 pad 1.78)
  other vias: 40.64,88.9
S$148  (via drill 0.81 pad 1.78)
  other vias: 43.18,88.9
S$149  (via drill 0.81 pad 1.78)
  other vias: 45.72,88.9
S$150  (via drill 0.81 pad 1.78)
  other vias: 48.26,88.9
S$151  (via drill 0.81 pad 1.78)
  other vias: 50.8,88.9
S$152
  Bottom 1.676: 117.79,83.19 117.47,83.19
S$153  (via drill 0.81 pad 1.78)
  other vias: 45.72,86.36
S$154  (via drill 0.81 pad 1.78)
  other vias: 45.72,83.82
S$155  (via drill 0.81 pad 1.78)
  other vias: 45.72,81.28
S$156  (via drill 0.81 pad 1.78)
  other vias: 45.72,78.74
S$157  (via drill 0.81 pad 1.78)
  other vias: 43.18,78.74
S$158  (via drill 0.81 pad 1.78)
  other vias: 43.18,81.28
S$159  (via drill 0.81 pad 1.78)
  other vias: 43.18,83.82
S$160  (via drill 0.81 pad 1.78)
  other vias: 43.18,86.36
S$161  (via drill 0.81 pad 1.78)
  other vias: 40.64,86.36
S$162  (via drill 0.81 pad 1.78)
  other vias: 40.64,83.82
S$163  (via drill 0.81 pad 1.78)
  other vias: 40.64,81.28
S$164  (via drill 0.81 pad 1.78)
  other vias: 40.64,78.74
S$165  (via drill 0.81 pad 1.78)
  other vias: 38.1,78.74
S$166  (via drill 0.81 pad 1.78)
  other vias: 38.1,81.28
S$167  (via drill 0.81 pad 1.78)
  other vias: 38.1,83.82
S$168  (via drill 0.81 pad 1.78)
  other vias: 38.1,86.36
S$169  (via drill 0.81 pad 1.78)
  other vias: 35.56,86.36
S$170  (via drill 0.81 pad 1.78)
  other vias: 35.56,83.82
S$171  (via drill 0.81 pad 1.78)
  other vias: 35.56,81.28
S$172  (via drill 0.81 pad 1.78)
  other vias: 35.56,78.74
S$173  (via drill 0.81 pad 1.78)
  other vias: 33.02,78.74
S$174  (via drill 0.81 pad 1.78)
  other vias: 33.02,81.28
S$175  (via drill 0.81 pad 1.78)
  other vias: 33.02,83.82
S$176  (via drill 0.81 pad 1.78)
  other vias: 33.02,86.36
S$177  (via drill 0.81 pad 1.78)
  other vias: 30.48,86.36
S$178  (via drill 0.81 pad 1.78)
  other vias: 30.48,83.82
S$179  (via drill 0.81 pad 1.78)
  other vias: 30.48,81.28
S$180  (via drill 0.81 pad 1.78)
  other vias: 30.48,78.74
S$181  (via drill 0.81 pad 1.78)
  other vias: 27.94,78.74
S$182  (via drill 0.81 pad 1.78)
  other vias: 27.94,81.28
S$183  (via drill 0.81 pad 1.78)
  other vias: 27.94,83.82
S$184  (via drill 0.81 pad 1.78)
  other vias: 27.94,86.36
S$185  (via drill 0.81 pad 1.78)
  other vias: 25.4,86.36
S$186  (via drill 0.81 pad 1.78)
  other vias: 25.4,83.82
S$187  (via drill 0.81 pad 1.78)
  other vias: 25.4,81.28
S$188  (via drill 0.81 pad 1.78)
  other vias: 25.4,78.74
S$189  (via drill 0.81 pad 1.78)
  other vias: 22.86,78.74
S$190  (via drill 0.81 pad 1.78)
  other vias: 22.86,81.28
S$191  (via drill 0.81 pad 1.78)
  other vias: 22.86,83.82
S$192  (via drill 0.81 pad 1.78)
  other vias: 22.86,86.36
S$193  (via drill 0.81 pad 1.78)
  other vias: 22.86,88.9
S$194  (via drill 0.81 pad 1.78)
  other vias: 22.86,91.44
S$195  (via drill 0.81 pad 1.78)
  other vias: 22.86,93.98
S$196  (via drill 0.81 pad 1.78)
  other vias: 22.86,96.52
S$197  (via drill 0.81 pad 1.78)
  other vias: 25.4,96.52
S$198  (via drill 0.81 pad 1.78)
  other vias: 27.94,96.52
S$199  (via drill 0.81 pad 1.78)
  other vias: 30.48,96.52
S$200  (via drill 0.81 pad 1.78)
  other vias: 33.02,96.52
S$201  (via drill 0.81 pad 1.78)
  other vias: 35.56,96.52
S$202  (via drill 0.81 pad 1.78)
  other vias: 38.1,96.52
S$203  (via drill 0.81 pad 1.78)
  other vias: 40.64,96.52
S$204  (via drill 0.81 pad 1.78)
  other vias: 43.18,96.52
S$205
  Bottom 1.778: 134.62,24.13 132.08,24.13 132.08,23.18 134.62,23.18 134.62,23.5
S$206
  Bottom 1.016: 125.73,34.29 127.95,34.29 127.95,30.48
S$207  (via drill 0.81 pad 1.78)
  other vias: 50.8,96.52
S$208
  Bottom 1.778: 134.62,11.43 132.08,11.43 132.08,12.38 134.62,12.38 134.62,11.75
S$209  (via drill 0.81 pad 1.78)
  other vias: 22.86,76.2
S$210  (via drill 0.81 pad 1.78)
  other vias: 25.4,76.2
S$211  (via drill 0.81 pad 1.78)
  other vias: 27.94,76.2
S$212  (via drill 0.81 pad 1.78)
  other vias: 30.48,76.2
S$213  (via drill 0.81 pad 1.78)
  other vias: 33.02,76.2
S$214  (via drill 0.81 pad 1.78)
  other vias: 35.56,76.2
S$215  (via drill 0.81 pad 1.78)
  other vias: 38.1,76.2
S$216  (via drill 0.81 pad 1.78)
  other vias: 38.1,73.66
S$217  (via drill 0.81 pad 1.78)
  other vias: 35.56,73.66
S$218  (via drill 0.81 pad 1.78)
  other vias: 33.02,73.66
S$219  (via drill 0.81 pad 1.78)
  other vias: 30.48,73.66
S$220  (via drill 0.81 pad 1.78)
  other vias: 27.94,73.66
S$221  (via drill 0.81 pad 1.78)
  other vias: 25.4,73.66
S$222  (via drill 0.81 pad 1.78)
  other vias: 22.86,73.66
S$223  (via drill 0.81 pad 1.78)
  other vias: 22.86,71.12
S$224  (via drill 0.81 pad 1.78)
  other vias: 25.4,71.12
S$225  (via drill 0.81 pad 1.78)
  other vias: 27.94,71.12
S$226  (via drill 0.81 pad 1.78)
  other vias: 30.48,71.12
S$227  (via drill 0.81 pad 1.78)
  other vias: 33.02,71.12
S$228  (via drill 0.81 pad 1.78)
  other vias: 35.56,71.12
S$229  (via drill 0.81 pad 1.78)
  other vias: 38.1,71.12
S$230  (via drill 0.81 pad 1.78)
  other vias: 38.1,68.58
S$231  (via drill 0.81 pad 1.78)
  other vias: 38.1,66.04
S$232  (via drill 0.81 pad 1.78)
  other vias: 38.1,63.5
S$233  (via drill 0.81 pad 1.78)
  other vias: 38.1,60.96
S$234  (via drill 0.81 pad 1.78)
  other vias: 35.56,60.96
S$235  (via drill 0.81 pad 1.78)
  other vias: 35.56,63.5
S$236  (via drill 0.81 pad 1.78)
  other vias: 35.56,66.04
S$237  (via drill 0.81 pad 1.78)
  other vias: 35.56,68.58
S$238  (via drill 0.81 pad 1.78)
  other vias: 33.02,68.58
S$239  (via drill 0.81 pad 1.78)
  other vias: 33.02,66.04
S$240  (via drill 0.81 pad 1.78)
  other vias: 33.02,63.5
S$241  (via drill 0.81 pad 1.78)
  other vias: 33.02,60.96
S$242  (via drill 0.81 pad 1.78)
  other vias: 30.48,60.96
S$243  (via drill 0.81 pad 1.78)
  other vias: 30.48,63.5
S$244  (via drill 0.81 pad 1.78)
  other vias: 30.48,66.04
S$245  (via drill 0.81 pad 1.78)
  other vias: 30.48,68.58
S$246  (via drill 0.81 pad 1.78)
  other vias: 27.94,68.58
S$247  (via drill 0.81 pad 1.78)
  other vias: 27.94,66.04
S$248  (via drill 0.81 pad 1.78)
  other vias: 27.94,63.5
S$249  (via drill 0.81 pad 1.78)
  other vias: 27.94,60.96
S$250  (via drill 0.81 pad 1.78)
  other vias: 25.4,60.96
S$251  (via drill 0.81 pad 1.78)
  other vias: 25.4,63.5
S$252  (via drill 0.81 pad 1.78)
  other vias: 25.4,66.04
S$253  (via drill 1.68 pad 3.81)  (1 unrouted)
  other vias: 58.42,3.32 133.38,3.34
S$254  (via drill 0.81 pad 1.78)
  other vias: 25.4,68.58
S$255  (via drill 0.81 pad 1.78)
  other vias: 22.86,68.58
S$256  (via drill 0.81 pad 1.78)
  other vias: 22.86,66.04
S$257  (via drill 0.81 pad 1.78)
  other vias: 22.86,63.5
S$258  (via drill 0.81 pad 1.78)
  other vias: 22.86,60.96
S$259  (via drill 0.81 pad 1.78)
  other vias: 22.86,58.42
S$260  (via drill 0.81 pad 1.78)
  other vias: 25.4,58.42
S$261  (via drill 0.81 pad 1.78)
  other vias: 27.94,58.42
S$262  (via drill 0.81 pad 1.78)
  other vias: 30.48,58.42
S$263  (via drill 0.81 pad 1.78)
  other vias: 33.02,58.42
S$264  (via drill 0.81 pad 1.78)
  other vias: 35.56,58.42
S$265  (via drill 0.81 pad 1.78)
  other vias: 38.1,58.42
S$267  (via drill 0.81 pad 1.78)
  other vias: 38.1,55.88
S$268  (via drill 0.81 pad 1.78)
  other vias: 35.56,55.88
S$269  (via drill 0.81 pad 1.78)
  other vias: 33.02,55.88
S$270  (via drill 0.81 pad 1.78)
  other vias: 30.48,55.88
S$271  (via drill 0.81 pad 1.78)
  other vias: 27.94,55.88
S$272  (via drill 0.81 pad 1.78)
  other vias: 25.4,55.88
S$273  (via drill 0.81 pad 1.78)
  other vias: 22.86,55.88
S$274  (via drill 0.81 pad 1.78)
  other vias: 22.86,53.34
S$275  (via drill 0.81 pad 1.78)
  other vias: 25.4,53.34
S$276  (via drill 0.81 pad 1.78)
  other vias: 27.94,53.34
S$277  (via drill 0.81 pad 1.78)
  other vias: 30.48,53.34
S$278  (via drill 0.81 pad 1.78)
  other vias: 33.02,53.34
S$279  (via drill 0.81 pad 1.78)
  other vias: 35.56,53.34
S$280  (via drill 0.81 pad 1.78)
  other vias: 38.1,53.34
S$281  (via drill 0.81 pad 1.78)
  other vias: 38.1,50.8
S$282  (via drill 0.81 pad 1.78)
  other vias: 38.1,48.26
S$283  (via drill 0.81 pad 1.78)
  other vias: 38.1,45.72
S$284  (via drill 0.81 pad 1.78)
  other vias: 38.1,43.18
S$285  (via drill 0.81 pad 1.78)
  other vias: 35.56,43.18
S$286  (via drill 0.81 pad 1.78)
  other vias: 35.56,45.72
S$287  (via drill 0.81 pad 1.78)
  other vias: 35.56,48.26
S$288  (via drill 0.81 pad 1.78)
  other vias: 35.56,50.8
S$289  (via drill 0.81 pad 1.78)
  other vias: 33.02,50.8
S$290  (via drill 0.81 pad 1.78)
  other vias: 33.02,48.26
S$291  (via drill 0.81 pad 1.78)
  other vias: 33.02,45.72
S$292  (via drill 0.81 pad 1.78)
  other vias: 33.02,43.18
S$293  (via drill 0.81 pad 1.78)
  other vias: 30.48,43.18
S$294  (via drill 0.81 pad 1.78)
  other vias: 30.48,45.72
S$295  (via drill 0.81 pad 1.78)
  other vias: 30.48,48.26
S$296  (via drill 0.81 pad 1.78)
  other vias: 30.48,50.8
S$297  (via drill 0.81 pad 1.78)
  other vias: 27.94,50.8
S$298  (via drill 0.81 pad 1.78)
  other vias: 27.94,48.26
S$299  (via drill 0.81 pad 1.78)
  other vias: 27.94,45.72
S$300  (via drill 0.81 pad 1.78)
  other vias: 27.94,43.18
S$301  (via drill 0.81 pad 1.78)
  other vias: 25.4,43.18
S$302  (via drill 0.81 pad 1.78)
  other vias: 25.4,45.72
S$303  (via drill 0.81 pad 1.78)
  other vias: 25.4,48.26
S$304  (via drill 0.81 pad 1.78)
  other vias: 25.4,50.8
S$305  (via drill 0.81 pad 1.78)
  other vias: 22.86,50.8
S$306  (via drill 0.81 pad 1.78)
  other vias: 22.86,48.26
S$307  (via drill 0.81 pad 1.78)
  other vias: 22.86,45.72
S$308  (via drill 0.81 pad 1.78)
  other vias: 22.86,43.18
S$309  (via drill 0.81 pad 1.78)
  other vias: 2.54,86.36
S$310  (via drill 0.81 pad 1.78)
  other vias: 5.08,86.36
S$311  (via drill 0.81 pad 1.78)
  other vias: 7.62,86.36
S$312  (via drill 0.81 pad 1.78)
  other vias: 10.16,86.36
S$313  (via drill 0.81 pad 1.78)
  other vias: 12.7,86.36
S$314  (via drill 0.81 pad 1.78)
  other vias: 15.24,86.36
S$315  (via drill 0.81 pad 1.78)
  other vias: 17.78,86.36
S$316  (via drill 0.81 pad 1.78)
  other vias: 17.78,83.82
S$317  (via drill 0.81 pad 1.78)
  other vias: 15.24,83.82
S$318  (via drill 0.81 pad 1.78)
  other vias: 12.7,83.82
S$319  (via drill 0.81 pad 1.78)
  other vias: 10.16,83.82
S$320  (via drill 0.81 pad 1.78)
  other vias: 7.62,83.82
S$321  (via drill 0.81 pad 1.78)
  other vias: 5.08,83.82
S$322  (via drill 0.81 pad 1.78)
  other vias: 2.54,83.82
S$323  (via drill 0.81 pad 1.78)
  other vias: 2.54,81.28
S$324  (via drill 0.81 pad 1.78)
  other vias: 5.08,81.28
S$325  (via drill 0.81 pad 1.78)
  other vias: 7.62,81.28
S$326  (via drill 0.81 pad 1.78)
  other vias: 10.16,81.28
S$327  (via drill 0.81 pad 1.78)
  other vias: 12.7,81.28
S$328  (via drill 0.81 pad 1.78)
  other vias: 15.24,81.28
S$329  (via drill 0.81 pad 1.78)
  other vias: 17.78,81.28
S$330  (via drill 0.81 pad 1.78)
  other vias: 17.78,78.74
S$331  (via drill 0.81 pad 1.78)
  other vias: 17.78,76.2
S$332  (via drill 0.81 pad 1.78)
  other vias: 17.78,73.66
S$333  (via drill 0.81 pad 1.78)
  other vias: 17.78,71.12
S$334  (via drill 0.81 pad 1.78)
  other vias: 15.24,71.12
S$335  (via drill 0.81 pad 1.78)
  other vias: 15.24,73.66
S$336  (via drill 0.81 pad 1.78)
  other vias: 15.24,76.2
S$337  (via drill 0.81 pad 1.78)
  other vias: 15.24,78.74
S$338  (via drill 0.81 pad 1.78)
  other vias: 12.7,78.74
S$339  (via drill 0.81 pad 1.78)
  other vias: 12.7,76.2
S$340  (via drill 0.81 pad 1.78)
  other vias: 12.7,73.66
S$341  (via drill 0.81 pad 1.78)
  other vias: 12.7,71.12
S$342  (via drill 0.81 pad 1.78)
  other vias: 10.16,71.12
S$343  (via drill 0.81 pad 1.78)
  other vias: 10.16,73.66
S$344  (via drill 0.81 pad 1.78)
  other vias: 10.16,76.2
S$345  (via drill 0.81 pad 1.78)
  other vias: 10.16,78.74
S$346  (via drill 0.81 pad 1.78)
  other vias: 7.62,78.74
S$347  (via drill 0.81 pad 1.78)
  other vias: 7.62,76.2
S$348  (via drill 0.81 pad 1.78)
  other vias: 7.62,73.66
S$349  (via drill 0.81 pad 1.78)
  other vias: 7.62,71.12
S$350  (via drill 0.81 pad 1.78)
  other vias: 5.08,71.12
S$351  (via drill 0.81 pad 1.78)
  other vias: 5.08,73.66
S$352  (via drill 0.81 pad 1.78)
  other vias: 5.08,76.2
S$353  (via drill 0.81 pad 1.78)
  other vias: 5.08,78.74
S$354  (via drill 0.81 pad 1.78)
  other vias: 2.54,78.74
S$355  (via drill 0.81 pad 1.78)
  other vias: 2.54,76.2
S$356  (via drill 0.81 pad 1.78)
  other vias: 2.54,73.66
S$357  (via drill 0.81 pad 1.78)
  other vias: 2.54,71.12
S$358  (via drill 0.81 pad 1.78)
  other vias: 2.54,68.58
S$359  (via drill 0.81 pad 1.78)
  other vias: 5.08,68.58
S$360  (via drill 0.81 pad 1.78)
  other vias: 7.62,68.58
S$361  (via drill 0.81 pad 1.78)
  other vias: 10.16,68.58
S$362  (via drill 0.81 pad 1.78)
  other vias: 12.7,68.58
S$363  (via drill 0.81 pad 1.78)
  other vias: 15.24,68.58
S$364  (via drill 0.81 pad 1.78)
  other vias: 17.78,68.58
S$365  (via drill 0.81 pad 1.78)
  other vias: 17.78,66.04
S$366  (via drill 0.81 pad 1.78)
  other vias: 15.24,66.04
S$367  (via drill 0.81 pad 1.78)
  other vias: 12.7,66.04
S$368  (via drill 0.81 pad 1.78)
  other vias: 10.16,66.04
S$369  (via drill 0.81 pad 1.78)
  other vias: 7.62,66.04
S$370  (via drill 0.81 pad 1.78)
  other vias: 5.08,66.04
S$371  (via drill 0.81 pad 1.78)
  other vias: 2.54,66.04
S$372  (via drill 0.81 pad 1.78)
  other vias: 2.54,63.5
S$373  (via drill 0.81 pad 1.78)
  other vias: 5.08,63.5
S$374  (via drill 0.81 pad 1.78)
  other vias: 7.62,63.5
S$375  (via drill 0.81 pad 1.78)
  other vias: 10.16,63.5
S$376  (via drill 0.81 pad 1.78)
  other vias: 12.7,63.5
S$377  (via drill 0.81 pad 1.78)
  other vias: 15.24,63.5
S$378  (via drill 0.81 pad 1.78)
  other vias: 17.78,63.5
S$379  (via drill 0.81 pad 1.78)
  other vias: 17.78,60.96
S$380  (via drill 0.81 pad 1.78)
  other vias: 17.78,58.42
S$381  (via drill 0.81 pad 1.78)
  other vias: 17.78,55.88
S$382  (via drill 0.81 pad 1.78)
  other vias: 17.78,53.34
S$383  (via drill 0.81 pad 1.78)
  other vias: 15.24,53.34
S$384  (via drill 0.81 pad 1.78)
  other vias: 15.24,55.88
S$385  (via drill 0.81 pad 1.78)
  other vias: 15.24,58.42
S$386  (via drill 0.81 pad 1.78)
  other vias: 15.24,60.96
S$387  (via drill 0.81 pad 1.78)
  other vias: 12.7,60.96
S$388  (via drill 0.81 pad 1.78)
  other vias: 12.7,58.42
S$389  (via drill 0.81 pad 1.78)
  other vias: 12.7,55.88
S$390  (via drill 0.81 pad 1.78)
  other vias: 12.7,53.34
S$391  (via drill 0.81 pad 1.78)
  other vias: 10.16,53.34
S$392  (via drill 0.81 pad 1.78)
  other vias: 10.16,55.88
S$393  (via drill 0.81 pad 1.78)
  other vias: 10.16,58.42
S$394  (via drill 0.81 pad 1.78)
  other vias: 10.16,60.96
S$395  (via drill 0.81 pad 1.78)
  other vias: 7.62,60.96
S$396  (via drill 0.81 pad 1.78)
  other vias: 7.62,58.42
S$397  (via drill 0.81 pad 1.78)
  other vias: 7.62,55.88
S$398  (via drill 0.81 pad 1.78)
  other vias: 7.62,53.34
S$399  (via drill 0.81 pad 1.78)
  other vias: 5.08,53.34
S$400  (via drill 0.81 pad 1.78)
  other vias: 5.08,55.88
S$401  (via drill 0.81 pad 1.78)
  other vias: 5.08,58.42
S$402  (via drill 0.81 pad 1.78)
  other vias: 5.08,60.96
S$403  (via drill 0.81 pad 1.78)
  other vias: 2.54,60.96
S$404  (via drill 0.81 pad 1.78)
  other vias: 2.54,58.42
S$405  (via drill 0.81 pad 1.78)
  other vias: 2.54,55.88
S$406  (via drill 0.81 pad 1.78)
  other vias: 2.54,53.34
S$407  (via drill 0.81 pad 1.78)
  other vias: 111.76,22.86
S$408  (via drill 0.81 pad 1.78)
  other vias: 114.3,22.86
S$409  (via drill 0.81 pad 1.78)
  other vias: 116.84,22.86
S$410  (via drill 0.81 pad 1.78)
  other vias: 119.38,22.86
S$411  (via drill 0.81 pad 1.78)
  other vias: 121.92,22.86
S$412  (via drill 0.81 pad 1.78)
  other vias: 124.46,22.86
S$413  (via drill 0.81 pad 1.78)
  other vias: 127,22.86
S$414  (via drill 0.81 pad 1.78)
  other vias: 127,20.32
S$415  (via drill 0.81 pad 1.78)
  other vias: 124.46,20.32
S$416  (via drill 0.81 pad 1.78)
  other vias: 121.92,20.32
S$417  (via drill 0.81 pad 1.78)
  other vias: 119.38,20.32
S$418  (via drill 0.81 pad 1.78)
  other vias: 116.84,20.32
S$419  (via drill 0.81 pad 1.78)
  other vias: 114.3,20.32
S$420  (via drill 0.81 pad 1.78)
  other vias: 111.76,20.32
S$421  (via drill 0.81 pad 1.78)
  other vias: 111.76,17.78
S$422  (via drill 0.81 pad 1.78)
  other vias: 114.3,17.78
S$423  (via drill 0.81 pad 1.78)
  other vias: 116.84,17.78
S$424  (via drill 0.81 pad 1.78)
  other vias: 119.38,17.78
S$425  (via drill 0.81 pad 1.78)
  other vias: 121.92,17.78
S$426  (via drill 0.81 pad 1.78)
  other vias: 124.46,17.78
S$427  (via drill 0.81 pad 1.78)
  other vias: 127,17.78
S$428  (via drill 0.81 pad 1.78)
  other vias: 127,15.24
S$429  (via drill 0.81 pad 1.78)
  other vias: 127,12.7
S$430  (via drill 0.81 pad 1.78)
  other vias: 127,10.16
S$431  (via drill 0.81 pad 1.78)
  other vias: 127,7.62
S$432  (via drill 0.81 pad 1.78)
  other vias: 124.46,7.62
S$433  (via drill 0.81 pad 1.78)
  other vias: 124.46,10.16
S$434  (via drill 0.81 pad 1.78)
  other vias: 124.46,12.7
S$435  (via drill 0.81 pad 1.78)
  other vias: 124.46,15.24
S$436  (via drill 0.81 pad 1.78)
  other vias: 121.92,15.24
S$437  (via drill 0.81 pad 1.78)
  other vias: 121.92,12.7
S$438  (via drill 0.81 pad 1.78)
  other vias: 121.92,10.16
S$439  (via drill 0.81 pad 1.78)
  other vias: 121.92,7.62
S$440  (via drill 0.81 pad 1.78)
  other vias: 119.38,7.62
S$441  (via drill 0.81 pad 1.78)
  other vias: 119.38,10.16
S$442  (via drill 0.81 pad 1.78)
  other vias: 119.38,12.7
S$443  (via drill 0.81 pad 1.78)
  other vias: 119.38,15.24
S$444  (via drill 0.81 pad 1.78)
  other vias: 116.84,15.24
S$445  (via drill 0.81 pad 1.78)
  other vias: 116.84,12.7
S$446  (via drill 0.81 pad 1.78)
  other vias: 116.84,10.16
S$447  (via drill 0.81 pad 1.78)
  other vias: 116.84,7.62
S$448  (via drill 0.81 pad 1.78)
  other vias: 114.3,7.62
S$449  (via drill 0.81 pad 1.78)
  other vias: 114.3,10.16
S$450  (via drill 0.81 pad 1.78)
  other vias: 114.3,12.7
S$451  (via drill 0.81 pad 1.78)
  other vias: 114.3,15.24
S$452  (via drill 0.81 pad 1.78)
  other vias: 111.76,15.24
S$453  (via drill 0.81 pad 1.78)
  other vias: 111.76,12.7
S$454  (via drill 0.81 pad 1.78)
  other vias: 111.76,10.16
S$455  (via drill 0.81 pad 1.78)
  other vias: 111.76,7.62
S$456  (via drill 0.81 pad 1.78)
  other vias: 93.98,22.86
S$457  (via drill 0.81 pad 1.78)
  other vias: 96.52,22.86
S$458  (via drill 0.81 pad 1.78)
  other vias: 99.06,22.86
S$459  (via drill 0.81 pad 1.78)
  other vias: 101.6,22.86
S$460  (via drill 0.81 pad 1.78)
  other vias: 104.14,22.86
S$461  (via drill 0.81 pad 1.78)
  other vias: 106.68,22.86
S$462  (via drill 0.81 pad 1.78)
  other vias: 109.22,22.86
S$463  (via drill 0.81 pad 1.78)
  other vias: 109.22,20.32
S$464  (via drill 0.81 pad 1.78)
  other vias: 106.68,20.32
S$465  (via drill 0.81 pad 1.78)
  other vias: 104.14,20.32
S$466  (via drill 0.81 pad 1.78)
  other vias: 101.6,20.32
S$467  (via drill 0.81 pad 1.78)
  other vias: 99.06,20.32
S$468  (via drill 0.81 pad 1.78)
  other vias: 96.52,20.32
S$469  (via drill 0.81 pad 1.78)
  other vias: 93.98,20.32
S$470  (via drill 0.81 pad 1.78)
  other vias: 93.98,17.78
S$471  (via drill 0.81 pad 1.78)
  other vias: 96.52,17.78
S$472  (via drill 0.81 pad 1.78)
  other vias: 99.06,17.78
S$473  (via drill 0.81 pad 1.78)
  other vias: 101.6,17.78
S$474  (via drill 0.81 pad 1.78)
  other vias: 104.14,17.78
S$475  (via drill 0.81 pad 1.78)
  other vias: 106.68,17.78
S$476  (via drill 0.81 pad 1.78)
  other vias: 109.22,17.78
S$477  (via drill 0.81 pad 1.78)
  other vias: 109.22,15.24
S$478  (via drill 0.81 pad 1.78)
  other vias: 109.22,12.7
S$479  (via drill 0.81 pad 1.78)
  other vias: 109.22,10.16
S$480  (via drill 0.81 pad 1.78)
  other vias: 109.22,7.62
S$481  (via drill 0.81 pad 1.78)
  other vias: 106.68,7.62
S$482  (via drill 0.81 pad 1.78)
  other vias: 106.68,10.16
S$483  (via drill 0.81 pad 1.78)
  other vias: 106.68,12.7
S$484  (via drill 0.81 pad 1.78)
  other vias: 106.68,15.24
S$485  (via drill 0.81 pad 1.78)
  other vias: 104.14,15.24
S$486  (via drill 0.81 pad 1.78)
  other vias: 104.14,12.7
S$487  (via drill 0.81 pad 1.78)
  other vias: 104.14,10.16
S$488  (via drill 0.81 pad 1.78)
  other vias: 104.14,7.62
S$489  (via drill 0.81 pad 1.78)
  other vias: 101.6,7.62
S$490  (via drill 0.81 pad 1.78)
  other vias: 101.6,10.16
S$491  (via drill 0.81 pad 1.78)
  other vias: 101.6,12.7
S$492  (via drill 0.81 pad 1.78)
  other vias: 101.6,15.24
S$493  (via drill 0.81 pad 1.78)
  other vias: 99.06,15.24
S$494  (via drill 0.81 pad 1.78)
  other vias: 99.06,12.7
S$495  (via drill 0.81 pad 1.78)
  other vias: 99.06,10.16
S$496  (via drill 0.81 pad 1.78)
  other vias: 99.06,7.62
S$497  (via drill 0.81 pad 1.78)
  other vias: 96.52,7.62
S$498  (via drill 0.81 pad 1.78)
  other vias: 96.52,10.16
S$499  (via drill 0.81 pad 1.78)
  other vias: 96.52,12.7
S$500  (via drill 0.81 pad 1.78)
  other vias: 96.52,15.24
S$501  (via drill 0.81 pad 1.78)
  other vias: 93.98,15.24
S$502  (via drill 0.81 pad 1.78)
  other vias: 93.98,12.7
S$503  (via drill 0.81 pad 1.78)
  other vias: 93.98,10.16
S$504  (via drill 0.81 pad 1.78)
  other vias: 93.98,7.62
S$505  (via drill 0.81 pad 1.78)
  other vias: 33.02,40.64
S$506  (via drill 0.81 pad 1.78)
  other vias: 78.74,22.86
S$507  (via drill 0.81 pad 1.78)
  other vias: 81.28,22.86
S$508  (via drill 0.81 pad 1.78)
  other vias: 83.82,22.86
S$509  (via drill 0.81 pad 1.78)
  other vias: 86.36,22.86
S$510  (via drill 0.81 pad 1.78)
  other vias: 88.9,22.86
S$511  (via drill 0.81 pad 1.78)
  other vias: 91.44,22.86
S$512  (via drill 0.81 pad 1.78)
  other vias: 91.44,20.32
S$513  (via drill 0.81 pad 1.78)
  other vias: 88.9,20.32
S$514  (via drill 0.81 pad 1.78)
  other vias: 86.36,20.32
S$515  (via drill 0.81 pad 1.78)
  other vias: 83.82,20.32
S$516  (via drill 0.81 pad 1.78)
  other vias: 81.28,20.32
S$517  (via drill 0.81 pad 1.78)
  other vias: 78.74,20.32
S$518  (via drill 0.81 pad 1.78)
  other vias: 35.56,40.64
S$519  (via drill 0.81 pad 1.78)
  other vias: 76.2,17.78
S$520  (via drill 0.81 pad 1.78)
  other vias: 78.74,17.78
S$521  (via drill 0.81 pad 1.78)
  other vias: 81.28,17.78
S$522  (via drill 0.81 pad 1.78)
  other vias: 83.82,17.78
S$523  (via drill 0.81 pad 1.78)
  other vias: 86.36,17.78
S$524  (via drill 0.81 pad 1.78)
  other vias: 88.9,17.78
S$525  (via drill 0.81 pad 1.78)
  other vias: 91.44,17.78
S$526  (via drill 0.81 pad 1.78)
  other vias: 91.44,15.24
S$527  (via drill 0.81 pad 1.78)
  other vias: 91.44,12.7
S$528  (via drill 0.81 pad 1.78)
  other vias: 91.44,10.16
S$529  (via drill 0.81 pad 1.78)
  other vias: 91.44,7.62
S$530  (via drill 0.81 pad 1.78)
  other vias: 88.9,7.62
S$531  (via drill 0.81 pad 1.78)
  other vias: 88.9,10.16
S$532  (via drill 0.81 pad 1.78)
  other vias: 88.9,12.7
S$533  (via drill 0.81 pad 1.78)
  other vias: 88.9,15.24
S$534  (via drill 0.81 pad 1.78)
  other vias: 86.36,15.24
S$535  (via drill 0.81 pad 1.78)
  other vias: 86.36,12.7
S$536  (via drill 0.81 pad 1.78)
  other vias: 86.36,10.16
S$537  (via drill 0.81 pad 1.78)
  other vias: 86.36,7.62
S$538  (via drill 0.81 pad 1.78)
  other vias: 83.82,7.62
S$539  (via drill 0.81 pad 1.78)
  other vias: 83.82,10.16
S$540  (via drill 0.81 pad 1.78)
  other vias: 83.82,12.7
S$541  (via drill 0.81 pad 1.78)
  other vias: 83.82,15.24
S$542  (via drill 0.81 pad 1.78)
  other vias: 81.28,15.24
S$543  (via drill 0.81 pad 1.78)
  other vias: 81.28,12.7
S$544  (via drill 0.81 pad 1.78)
  other vias: 81.28,10.16
S$545  (via drill 0.81 pad 1.78)
  other vias: 81.28,7.62
S$546  (via drill 0.81 pad 1.78)
  other vias: 78.74,7.62
S$547  (via drill 0.81 pad 1.78)
  other vias: 78.74,10.16
S$548  (via drill 0.81 pad 1.78)
  other vias: 78.74,12.7
S$549  (via drill 0.81 pad 1.78)
  other vias: 78.74,15.24
S$550  (via drill 0.81 pad 1.78)
  other vias: 76.2,15.24
S$551  (via drill 0.81 pad 1.78)
  other vias: 76.2,12.7
S$552  (via drill 0.81 pad 1.78)
  other vias: 76.2,10.16
S$553  (via drill 0.81 pad 1.78)
  other vias: 76.2,7.62
S$554  (via drill 0.81 pad 1.78)
  other vias: 45.72,22.86
S$555  (via drill 0.81 pad 1.78)
  other vias: 48.26,22.86
S$556  (via drill 0.81 pad 1.78)
  other vias: 50.8,22.86
S$557  (via drill 0.81 pad 1.78)
  other vias: 53.34,22.86
S$558  (via drill 0.81 pad 1.78)
  other vias: 55.88,22.86
S$559  (via drill 0.81 pad 1.78)
  other vias: 58.42,22.86
S$560  (via drill 0.81 pad 1.78)
  other vias: 60.96,22.86
S$561  (via drill 0.81 pad 1.78)
  other vias: 60.96,20.32
S$562  (via drill 0.81 pad 1.78)
  other vias: 58.42,20.32
S$563  (via drill 0.81 pad 1.78)
  other vias: 55.88,20.32
S$564  (via drill 0.81 pad 1.78)
  other vias: 53.34,20.32
S$565  (via drill 0.81 pad 1.78)
  other vias: 50.8,20.32
S$566  (via drill 0.81 pad 1.78)
  other vias: 48.26,20.32
S$567  (via drill 0.81 pad 1.78)
  other vias: 45.72,20.32
S$568  (via drill 0.81 pad 1.78)
  other vias: 45.72,17.78
S$569  (via drill 0.81 pad 1.78)
  other vias: 48.26,17.78
S$570  (via drill 0.81 pad 1.78)
  other vias: 50.8,17.78
S$571  (via drill 0.81 pad 1.78)
  other vias: 53.34,17.78
S$572  (via drill 0.81 pad 1.78)
  other vias: 55.88,17.78
S$573  (via drill 0.81 pad 1.78)
  other vias: 58.42,17.78
S$574  (via drill 0.81 pad 1.78)
  other vias: 60.96,17.78
S$575  (via drill 0.81 pad 1.78)
  other vias: 60.96,15.24
S$576  (via drill 0.81 pad 1.78)
  other vias: 60.96,12.7
S$577  (via drill 0.81 pad 1.78)
  other vias: 60.96,10.16
S$578
  Bottom 1.676: 129.22,2.54 63.82,2.54 63.82,24.13
S$579
  Bottom 1.676: 63.82,3.81 63.82,24.45
S$580  (via drill 0.81 pad 1.78)
  other vias: 58.42,10.16
S$581  (via drill 0.81 pad 1.78)
  other vias: 58.42,12.7
S$582  (via drill 0.81 pad 1.78)
  other vias: 58.42,15.24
